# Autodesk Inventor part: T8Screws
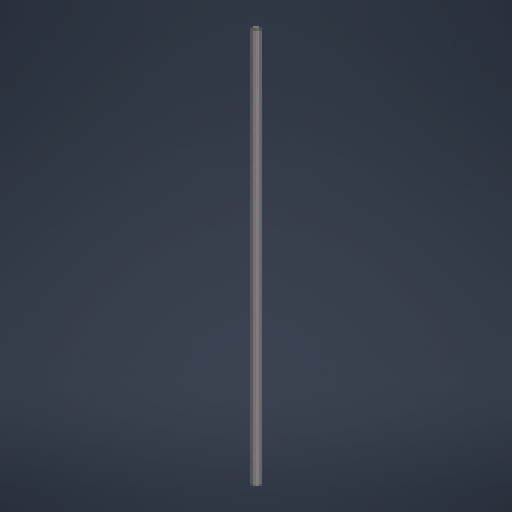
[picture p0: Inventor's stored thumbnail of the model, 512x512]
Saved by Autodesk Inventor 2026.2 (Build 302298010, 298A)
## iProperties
Created: 2026-04
Part Number: T8Screws
Material: 스테인리스스틸
Document SubType Name: Modeling
Designer: work
Density: 8 g/cm^3
Appearance: 반연마
Author: work
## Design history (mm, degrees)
sketch "스케치1"
  geometry: C1 r 4 at (0, 0); 1 further point
  constraints: 1 centre point, 1 coincident
  dimensions: "d0" = 8 diameter of C1
extrude "돌출1" new body sketch "스케치1" distance "d1" = 450; taper "d2" = 0 deg
chamfer "모따기1" distance "d3" = 1; stored, may be unused: second distance "d4" = 2, angle "d5" = 45 deg
feature "스레드1" dims "d6" = 298, "d7" = 0
node "솔리드1"
feature "A9D066F2-1C7D-4E18-AEED-F7BC21143FA4" dims "d6" = 298, "d7" = 0
